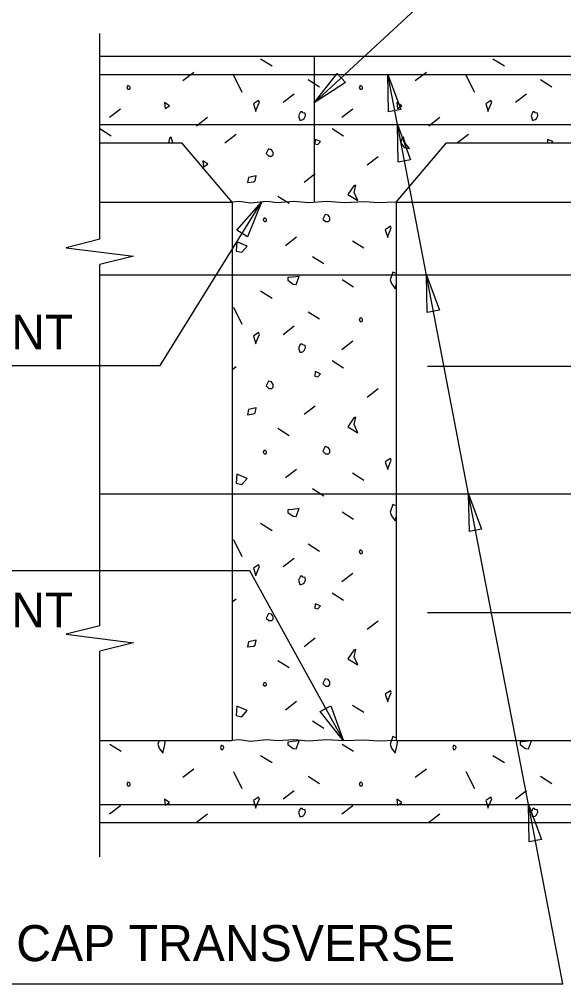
# Model space of a CAD drawing. Extents: x 0 to 34, y 0 to 23.5.
# Drawn here: x 12.662 to 15.025, y 15.614 to 19.798 of the extents above; entities that cross this region are included whole.
import ezdxf

# ---------------------------------------------------------------- set-up
doc = ezdxf.new("R2010")
doc.units = 0
for name, color, linetype in [('BRDG_ANNO_General-Notes', 7, 'Continuous'), ('BRDG_BASE_Obj-Line', 7, 'Continuous'), ('BRDG_BASE_Pattern', 7, 'Continuous'), ('BRDG_BASE_Rebar', 7, 'Continuous')]:
    doc.layers.add(name, color=color, linetype=linetype)

msp = doc.modelspace()

# ---------------------------------------------------------------- linework, layer by layer
at = {"layer": 'BRDG_ANNO_General-Notes'}
for p, q in [((14.5249, 19.9752), (13.9414, 19.4354)), ((13.9414, 19.4354), (14.0407, 19.5636)), ((14.0407, 19.5636), (14.077, 19.5245)), ((14.2646, 19.3966), (14.2605, 19.5587)), ((14.2605, 19.5587), (14.317, 19.4066)), ((14.3026, 19.341), (14.2605, 19.5587)), ((14.077, 19.5245), (13.9414, 19.4354)), ((14.317, 19.4066), (14.2646, 19.3966)), ((14.3066, 19.1789), (14.3025, 19.341)), ((14.3025, 19.341), (14.359, 19.1889)), ((14.4284, 18.6879), (14.3025, 19.341)), ((14.359, 19.1889), (14.3066, 19.1789)), ((13.2729, 18.2954), (13.7135, 19.0045)), ((13.6064, 18.8827), (13.7135, 19.0045)), ((13.7135, 19.0045), (13.6517, 18.8545)), ((13.6517, 18.8545), (13.6064, 18.8827)), ((14.6116, 17.7379), (14.4284, 18.6879)), ((14.4325, 18.5257), (14.4284, 18.6879)), ((14.4284, 18.6879), (14.4849, 18.5358)), ((14.4849, 18.5358), (14.4325, 18.5257)), ((11.3562, 18.2954), (13.2729, 18.2954)), ((14.871, 16.392), (14.6116, 17.7379)), ((14.6157, 17.5757), (14.6116, 17.7379)), ((14.6116, 17.7379), (14.668, 17.5858)), ((14.668, 17.5858), (14.6157, 17.5757)), ((11.3562, 17.4069), (13.6608, 17.4069)), ((13.6608, 17.4069), (14.0683, 16.6672)), ((13.9677, 16.7945), (14.0144, 16.8203)), ((14.0144, 16.8203), (14.0683, 16.6672)), ((14.0683, 16.6672), (13.9677, 16.7945)), ((15.021, 15.6141), (14.871, 16.392)), ((14.8752, 16.2299), (14.871, 16.392)), ((14.871, 16.392), (14.9275, 16.2399)), ((14.9275, 16.2399), (14.8752, 16.2299)), ((10.8448, 15.6141), (15.021, 15.6141))]:
    msp.add_line(p, q, dxfattribs=at)
at = {"layer": 'BRDG_BASE_Obj-Line'}
for p, q in [((13.0112, 18.8436), (13.0112, 19.7368)), ((13.0112, 19.6379), (17.3654, 19.6379)), ((13.9414, 19.6379), (13.9414, 19.0045)), ((13.0112, 19.2618), (13.3674, 19.2618)), ((13.5852, 19.0045), (13.3674, 19.2618)), ((14.2977, 19.0045), (14.5154, 19.2618)), ((14.5154, 19.2618), (17.3654, 19.2618)), ((13.0112, 19.0045), (13.5852, 19.0045)), ((13.5852, 19.0045), (13.5852, 16.6691)), ((14.2977, 19.0067), (14.2977, 16.6691)), ((14.2977, 19.0045), (16.0789, 19.0045)), ((13.0112, 18.8436), (12.8654, 18.8071)), ((12.8654, 18.8071), (13.157, 18.7707)), ((13.157, 18.7707), (13.0112, 18.7342)), ((13.0112, 17.1665), (13.0112, 18.7342)), ((13.0112, 17.1665), (12.8654, 17.1301)), ((12.8654, 17.1301), (13.157, 17.0936)), ((13.157, 17.0936), (13.0112, 17.0571)), ((13.0112, 16.1639), (13.0112, 17.0571)), ((13.0112, 16.6691), (13.5852, 16.6691)), ((14.2977, 16.6691), (17.3654, 16.6691)), ((13.0112, 16.3129), (17.3654, 16.3129))]:
    msp.add_line(p, q, dxfattribs=at)
for points in [[(14.2977, 19.0045), (14.2184, 19.0012), (14.1615, 19.0067), (14.0712, 19.0025), (13.9967, 19.0069), (13.9162, 19.0015), (13.8534, 19.0071), (13.7828, 19.0025), (13.7357, 19.0079), (13.6651, 19.0008), (13.616, 19.0071), (13.5852, 19.0045)], [(14.2977, 16.6691), (14.2184, 16.6658), (14.1615, 16.6713), (14.0712, 16.6671), (13.9967, 16.6715), (13.9162, 16.6661), (13.8534, 16.6717), (13.7828, 16.6671), (13.7357, 16.6724), (13.6651, 16.6654), (13.616, 16.6717), (13.5852, 16.6691)]]:
    msp.add_lwpolyline(points, dxfattribs=at)
at = {"layer": 'BRDG_BASE_Pattern'}
for p, q in [((13.709, 19.6269), (13.7585, 19.5956)), ((14.7174, 19.6269), (14.7669, 19.5956)), ((13.4199, 19.5672), (13.3718, 19.5306)), ((13.5915, 19.5561), (13.6282, 19.4826)), ((14.4283, 19.5672), (14.3802, 19.5306)), ((14.5999, 19.5561), (14.6366, 19.4826)), ((13.9154, 19.5366), (13.9648, 19.5053)), ((14.9238, 19.5366), (14.9732, 19.5053)), ((13.8549, 19.4734), (13.8068, 19.4368)), ((14.8633, 19.4734), (14.8152, 19.4368)), ((13.1011, 19.4084), (13.053, 19.3718)), ((14.1095, 19.4084), (14.0614, 19.3718)), ((13.4783, 19.3715), (13.4302, 19.3349)), ((14.4867, 19.3715), (14.4385, 19.3349)), ((13.0112, 19.3245), (13.0607, 19.2932)), ((13.6026, 19.2976), (13.5544, 19.2609)), ((14.0196, 19.3245), (14.0691, 19.2932)), ((14.6109, 19.2976), (14.564, 19.2618)), ((14.2198, 19.202), (14.1717, 19.1654)), ((13.9463, 19.1273), (13.8982, 19.0907)), ((13.7833, 19.0312), (13.8328, 19)), ((13.8652, 18.8526), (13.8171, 18.8159)), ((14.1077, 18.8376), (14.1571, 18.8066)), ((13.9341, 18.7693), (13.9836, 18.7381)), ((14.0627, 18.6686), (14.1121, 18.6373)), ((13.709, 18.6195), (13.7585, 18.5883)), ((13.5915, 18.5487), (13.6282, 18.4752)), ((13.9154, 18.5292), (13.9648, 18.498)), ((13.8549, 18.4661), (13.8068, 18.4295)), ((14.1095, 18.4011), (14.0614, 18.3645)), ((13.6026, 18.2902), (13.5852, 18.277)), ((14.0196, 18.3171), (14.0691, 18.2859)), ((14.2198, 18.1946), (14.1717, 18.158)), ((13.9463, 18.1199), (13.8982, 18.0833)), ((13.7833, 18.0239), (13.8328, 17.9927)), ((13.8652, 17.8452), (13.8171, 17.8086)), ((14.1077, 17.8303), (14.1571, 17.7992)), ((13.9341, 17.762), (13.9836, 17.7307)), ((14.0627, 17.6612), (14.1121, 17.6299)), ((13.709, 17.6122), (13.7585, 17.5809)), ((13.5915, 17.5414), (13.6282, 17.4679)), ((13.9154, 17.5219), (13.9648, 17.4906)), ((13.8549, 17.4587), (13.8068, 17.4221)), ((14.1095, 17.3938), (14.0614, 17.3571)), ((13.6026, 17.2829), (13.5852, 17.2696)), ((14.0196, 17.3098), (14.0691, 17.2785)), ((14.2198, 17.1873), (14.1717, 17.1507)), ((13.9463, 17.1126), (13.8982, 17.076)), ((13.7833, 17.0165), (13.8328, 16.9853)), ((13.8652, 16.8379), (13.8171, 16.8012)), ((14.1077, 16.8229), (14.1571, 16.7919)), ((13.9341, 16.7546), (13.9836, 16.7234)), ((13.0543, 16.6539), (13.1037, 16.6226)), ((14.0627, 16.6539), (14.1121, 16.6226)), ((13.709, 16.6048), (13.7585, 16.5736)), ((14.7174, 16.6048), (14.7669, 16.5736)), ((13.4199, 16.5452), (13.3718, 16.5085)), ((13.5915, 16.5341), (13.6282, 16.4605)), ((14.4283, 16.5452), (14.3802, 16.5085)), ((14.5999, 16.5341), (14.6366, 16.4605)), ((13.9154, 16.5145), (13.9648, 16.4833)), ((14.9238, 16.5145), (14.9732, 16.4833)), ((13.8549, 16.4514), (13.8068, 16.4148)), ((14.8633, 16.4514), (14.8152, 16.4148)), ((13.1011, 16.3864), (13.053, 16.3498)), ((14.1095, 16.3864), (14.0614, 16.3498)), ((13.4783, 16.3495), (13.4302, 16.3129)), ((14.4867, 16.3495), (14.4385, 16.3129))]:
    msp.add_line(p, q, dxfattribs=at)
for points in [[(13.1326, 19.5105), (13.128, 19.5003), (13.1334, 19.4947), (13.14, 19.4947), (13.1427, 19.4977), (13.1427, 19.5031), (13.1418, 19.5057), (13.139, 19.5087)], [(14.141, 19.5105), (14.1364, 19.5003), (14.1418, 19.4947), (14.1484, 19.4947), (14.1511, 19.4977), (14.1511, 19.5031), (14.1502, 19.5057), (14.1473, 19.5087)], [(13.2915, 19.4367), (13.2952, 19.4109), (13.3137, 19.422)], [(13.6776, 19.4313), (13.689, 19.3981), (13.689, 19.4017), (13.7036, 19.4386), (13.6999, 19.446)], [(14.2999, 19.4367), (14.3036, 19.4109), (14.3221, 19.422)], [(14.6859, 19.4313), (14.6973, 19.3981), (14.6973, 19.4017), (14.712, 19.4386), (14.7083, 19.446)], [(13.8742, 19.3796), (13.88, 19.3611), (13.8853, 19.3611), (13.8928, 19.363), (13.8982, 19.3683), (13.9036, 19.3796), (13.9021, 19.3905), (13.8928, 19.3924), (13.8889, 19.3962), (13.8816, 19.3962)], [(14.8826, 19.3796), (14.8884, 19.3611), (14.8937, 19.3611), (14.9012, 19.363), (14.9066, 19.3683), (14.912, 19.3796), (14.9105, 19.3905), (14.9012, 19.3924), (14.8973, 19.3962), (14.8899, 19.3962)], [(13.9459, 19.2771), (13.945, 19.2573), (13.9569, 19.2546), (13.9684, 19.2679)], [(14.3223, 19.2826), (14.3183, 19.2619), (14.332, 19.2416), (14.3551, 19.237), (14.3367, 19.2614), (14.3288, 19.2867)], [(13.7429, 19.2355), (13.7336, 19.2153), (13.7445, 19.2041), (13.7577, 19.2041), (13.7631, 19.2099), (13.7631, 19.2207), (13.7613, 19.226), (13.7556, 19.232)], [(13.4581, 19.1836), (13.4618, 19.1578), (13.4803, 19.1689)], [(13.6559, 19.1119), (13.6522, 19.0899), (13.6781, 19.0936), (13.6854, 19.0972), (13.6891, 19.1193)], [(14.1132, 19.0762), (14.0875, 19.0377), (14.1308, 19.0118), (14.115, 19.0468), (14.1217, 19.0789)], [(13.7245, 18.9361), (13.7198, 18.926), (13.7253, 18.9204), (13.7319, 18.9204), (13.7346, 18.9233), (13.7346, 18.9288), (13.7337, 18.9314), (13.7308, 18.9344)], [(13.989, 18.9518), (13.9797, 18.9316), (13.9905, 18.9203), (14.0038, 18.9203), (14.0092, 18.9262), (14.0092, 18.937), (14.0073, 18.9423), (14.0016, 18.9482)], [(14.2502, 18.8854), (14.2615, 18.8521), (14.2615, 18.8557), (14.2763, 18.8927), (14.2726, 18.9001)], [(13.6053, 18.8322), (13.6035, 18.7927), (13.6274, 18.7871), (13.6504, 18.8138)], [(13.8487, 18.6791), (13.8267, 18.6772), (13.8267, 18.6661), (13.8506, 18.6496), (13.8636, 18.6478), (13.8765, 18.6827)], [(14.141, 18.5031), (14.1364, 18.493), (14.1418, 18.4873), (14.1484, 18.4873), (14.1511, 18.4903), (14.1511, 18.4957), (14.1502, 18.4984), (14.1473, 18.5014)], [(13.6776, 18.424), (13.689, 18.3907), (13.689, 18.3943), (13.7036, 18.4313), (13.6999, 18.4386)], [(13.8742, 18.3722), (13.88, 18.3538), (13.8853, 18.3538), (13.8928, 18.3556), (13.8982, 18.361), (13.9036, 18.3722), (13.9021, 18.3832), (13.8928, 18.3851), (13.8889, 18.3889), (13.8816, 18.3889)], [(13.9459, 18.2698), (13.945, 18.25), (13.9569, 18.2472), (13.9684, 18.2606)], [(13.7429, 18.2282), (13.7336, 18.208), (13.7445, 18.1967), (13.7577, 18.1967), (13.7631, 18.2026), (13.7631, 18.2134), (13.7613, 18.2187), (13.7556, 18.2246)], [(13.6559, 18.1046), (13.6522, 18.0826), (13.6781, 18.0862), (13.6854, 18.0898), (13.6891, 18.112)], [(14.1132, 18.0689), (14.0875, 18.0304), (14.1308, 18.0044), (14.115, 18.0395), (14.1217, 18.0716)], [(13.7245, 17.9288), (13.7198, 17.9187), (13.7253, 17.9131), (13.7319, 17.9131), (13.7346, 17.916), (13.7346, 17.9214), (13.7337, 17.9241), (13.7308, 17.927)], [(13.989, 17.9444), (13.9797, 17.9242), (13.9905, 17.913), (14.0038, 17.913), (14.0092, 17.9189), (14.0092, 17.9296), (14.0073, 17.9349), (14.0016, 17.9409)], [(14.2502, 17.878), (14.2615, 17.8448), (14.2615, 17.8483), (14.2763, 17.8854), (14.2726, 17.8927)], [(13.6053, 17.8249), (13.6035, 17.7853), (13.6274, 17.7797), (13.6504, 17.8065)], [(13.8487, 17.6717), (13.8267, 17.6698), (13.8267, 17.6588), (13.8506, 17.6423), (13.8636, 17.6404), (13.8765, 17.6754)], [(14.141, 17.4958), (14.1364, 17.4856), (14.1418, 17.48), (14.1484, 17.48), (14.1511, 17.483), (14.1511, 17.4884), (14.1502, 17.491), (14.1473, 17.494)], [(13.6776, 17.4166), (13.689, 17.3834), (13.689, 17.387), (13.7036, 17.424), (13.6999, 17.4313)], [(13.8742, 17.3649), (13.88, 17.3465), (13.8853, 17.3465), (13.8928, 17.3483), (13.8982, 17.3536), (13.9036, 17.3649), (13.9021, 17.3758), (13.8928, 17.3778), (13.8889, 17.3816), (13.8816, 17.3816)], [(13.9459, 17.2624), (13.945, 17.2427), (13.9569, 17.2399), (13.9684, 17.2532)], [(13.7429, 17.2208), (13.7336, 17.2006), (13.7445, 17.1894), (13.7577, 17.1894), (13.7631, 17.1953), (13.7631, 17.206), (13.7613, 17.2114), (13.7556, 17.2173)], [(13.6559, 17.0972), (13.6522, 17.0752), (13.6781, 17.0789), (13.6854, 17.0825), (13.6891, 17.1046)], [(14.1132, 17.0616), (14.0875, 17.023), (14.1308, 16.9971), (14.115, 17.0321), (14.1217, 17.0642)], [(13.7245, 16.9215), (13.7198, 16.9114), (13.7253, 16.9057), (13.7319, 16.9057), (13.7346, 16.9086), (13.7346, 16.9141), (13.7337, 16.9167), (13.7308, 16.9197)], [(13.989, 16.9371), (13.9797, 16.9169), (13.9905, 16.9056), (14.0038, 16.9056), (14.0092, 16.9115), (14.0092, 16.9223), (14.0073, 16.9276), (14.0016, 16.9335)], [(14.2502, 16.8707), (14.2615, 16.8374), (14.2615, 16.841), (14.2763, 16.878), (14.2726, 16.8854)], [(13.6053, 16.8176), (13.6035, 16.778), (13.6274, 16.7724), (13.6504, 16.7991)], [(13.8487, 16.6644), (13.8267, 16.6625), (13.8267, 16.6515), (13.8506, 16.6349), (13.8636, 16.6331), (13.8765, 16.668)], [(14.8571, 16.6644), (14.8351, 16.6625), (14.8351, 16.6515), (14.859, 16.6349), (14.872, 16.6331), (14.8849, 16.668)], [(13.5345, 16.6391), (13.5374, 16.6298), (13.5401, 16.6298), (13.5439, 16.6308), (13.5466, 16.6334), (13.5492, 16.6391), (13.5485, 16.6446), (13.5439, 16.6455), (13.5419, 16.6474), (13.5382, 16.6474)], [(14.5429, 16.6391), (14.5458, 16.6298), (14.5485, 16.6298), (14.5522, 16.6308), (14.5549, 16.6334), (14.5576, 16.6391), (14.5569, 16.6446), (14.5522, 16.6455), (14.5503, 16.6474), (14.5466, 16.6474)], [(13.1326, 16.4884), (13.128, 16.4783), (13.1334, 16.4727), (13.14, 16.4727), (13.1427, 16.4756), (13.1427, 16.481), (13.1418, 16.4837), (13.139, 16.4867)], [(14.141, 16.4884), (14.1364, 16.4783), (14.1418, 16.4727), (14.1484, 16.4727), (14.1511, 16.4756), (14.1511, 16.481), (14.1502, 16.4837), (14.1473, 16.4867)], [(13.2915, 16.4147), (13.2952, 16.3889), (13.3137, 16.3999)], [(13.6776, 16.4093), (13.689, 16.376), (13.689, 16.3796), (13.7036, 16.4166), (13.6999, 16.424)], [(14.2999, 16.4147), (14.3036, 16.3889), (14.3221, 16.3999)], [(14.6859, 16.4093), (14.6973, 16.376), (14.6973, 16.3796), (14.712, 16.4166), (14.7083, 16.424)], [(13.8742, 16.3576), (13.88, 16.3391), (13.8853, 16.3391), (13.8928, 16.3409), (13.8982, 16.3463), (13.9036, 16.3576), (13.9021, 16.3685), (13.8928, 16.3704), (13.8889, 16.3742), (13.8816, 16.3742)], [(14.8826, 16.3576), (14.8884, 16.3391), (14.8937, 16.3391), (14.9012, 16.3409), (14.9066, 16.3463), (14.912, 16.3576), (14.9105, 16.3685), (14.9012, 16.3704), (14.8973, 16.3742), (14.8899, 16.3742)]]:
    msp.add_lwpolyline(points, close=True, dxfattribs=at)
for points in [[(13.314, 19.2826), (13.3099, 19.2619), (13.3099, 19.2618)], [(13.3282, 19.2618), (13.3204, 19.2867), (13.314, 19.2826)], [(14.9543, 19.2771), (14.9536, 19.2618)], [(14.9716, 19.2618), (14.9768, 19.2679), (14.9543, 19.2771)], [(14.2825, 18.701), (14.2713, 18.6679), (14.277, 18.6513), (14.2935, 18.6292), (14.2977, 18.6457)], [(14.2977, 18.6952), (14.2825, 18.701)], [(14.2825, 17.6936), (14.2713, 17.6605), (14.277, 17.644), (14.2935, 17.6218), (14.2977, 17.6383)], [(14.2977, 17.6878), (14.2825, 17.6936)], [(13.2683, 16.6691), (13.2629, 16.6532), (13.2686, 16.6366), (13.2852, 16.6145), (13.2925, 16.644), (13.2967, 16.6691)], [(14.2825, 16.6863), (14.2713, 16.6532), (14.277, 16.6366), (14.2935, 16.6145), (14.3009, 16.644), (14.3051, 16.6691)], [(14.2977, 16.6805), (14.2825, 16.6863)]]:
    msp.add_lwpolyline(points, dxfattribs=at)
at = {"layer": 'BRDG_BASE_Rebar'}
for p, q in [((13.0112, 19.5587), (17.3654, 19.5587)), ((13.0112, 19.341), (17.3654, 19.341)), ((17.3654, 18.6879), (13.0112, 18.6879)), ((17.3654, 18.292), (14.4337, 18.292)), ((17.3654, 17.7379), (13.0112, 17.7379)), ((17.3654, 17.2233), (14.4337, 17.2233)), ((13.0112, 16.392), (17.3654, 16.392))]:
    msp.add_line(p, q, dxfattribs=at)

# ---------------------------------------------------------------- texts
at = {"layer": 'BRDG_ANNO_General-Notes'}
for s, height, p in [('CONST. JOINT', 0.150417, (11.4987, 18.3659)), ('CONST. JOINT', 0.150417, (11.4987, 17.1602)), ('SLAB AND BENT CAP TRANSVERSE', 0.15625, (10.9418, 15.712))]:
    msp.add_text(s, height=height, dxfattribs=at).set_placement(p)

doc.saveas('drawing.dxf')
